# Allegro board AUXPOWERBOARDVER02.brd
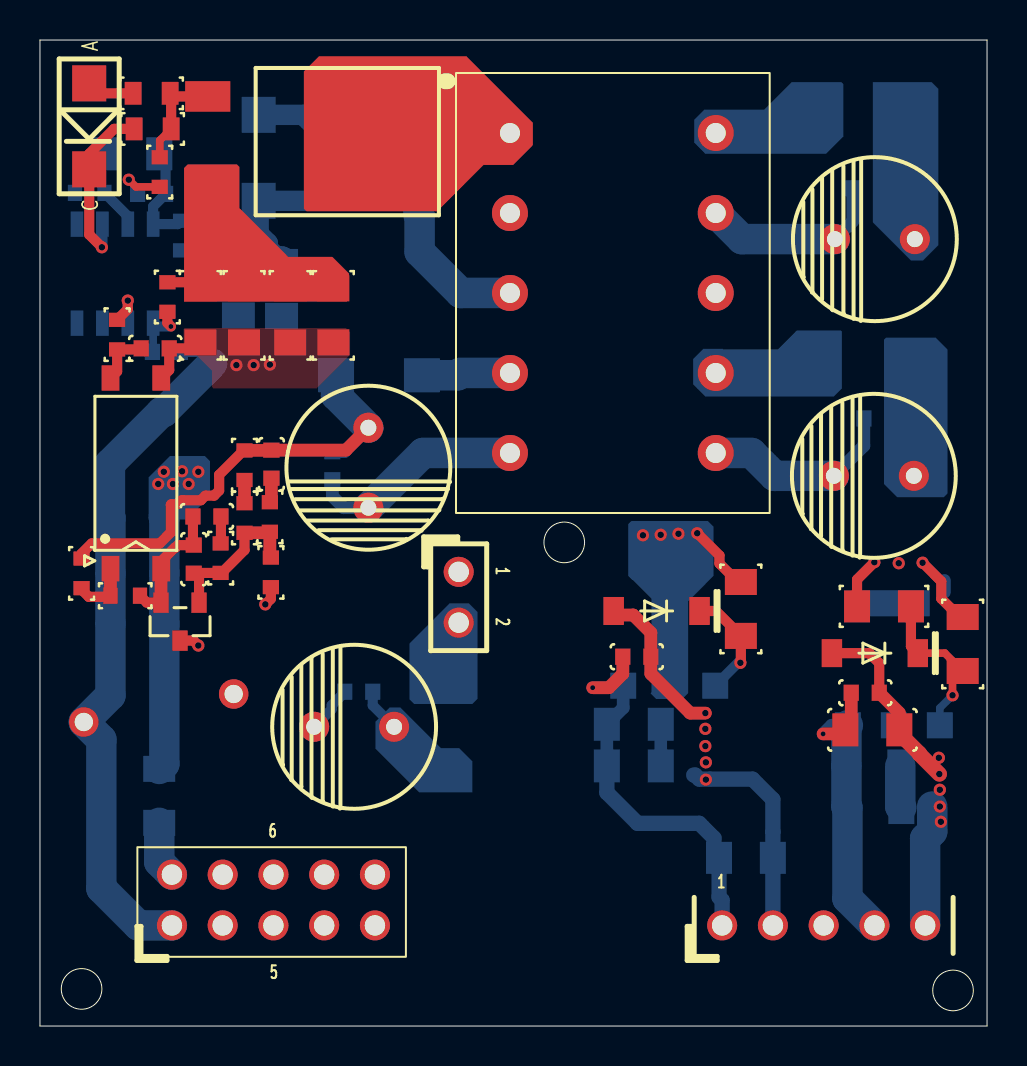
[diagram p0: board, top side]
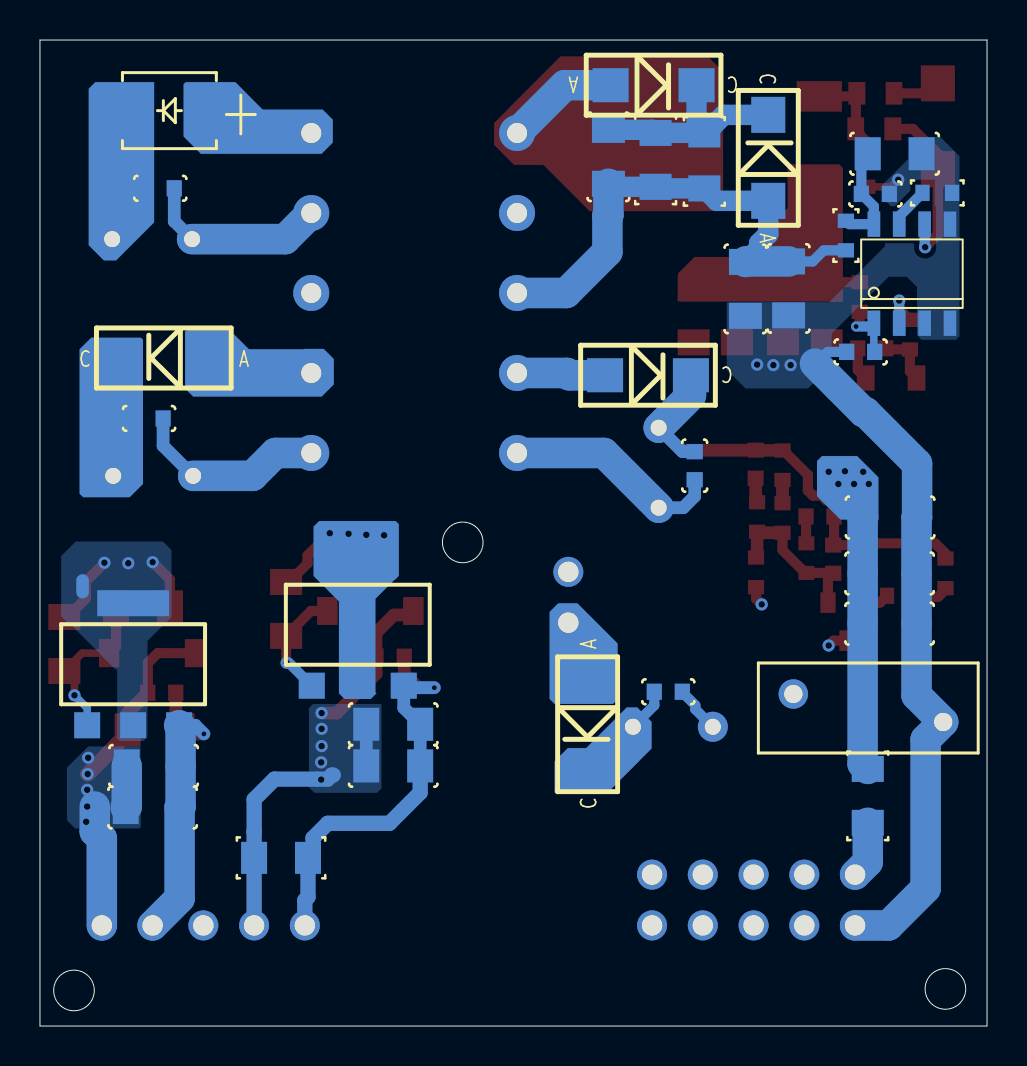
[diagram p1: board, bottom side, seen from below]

Outline 47.4 x 49.3 mm; copper layers: TOP, LAYER1, LAYER2, BOTTOM. Coordinates in mm from the lower left corner of the outline.
Outline path: circle c2.08,1.85 r1.02 ; circle c26.24,24.18 r1.02 ; circle c45.69,1.78 r1.02 ; 0,49.3 0,0 47.4,0 47.4,49.3 0,49.3

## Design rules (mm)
net group HVDC_SW: nets N16531900 N16531954
net group MVDC_SEC: nets N16668742 P_15V
net group LVDC_PRI: nets N16901051 N16901170 N16901172
net group LVDC_SEC: nets N16899196 N16899206 N16900214 N16900266
nets with their own width: min track width 0.8; nets 5V CAN_GND D_6.5V DGND N16531988 N16540909 N16669014 N16669754 N16669797 N16867048 N16899220 S_15V SGND

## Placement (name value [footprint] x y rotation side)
C22  1u  [C0603]  41.38 41.88 180 bottom
C67  1000pF  [C0603]  7.7 23.34 270 top
C95  100n  [C0603]  8.36 25.48 0 top
C111  1u  [C1206]  18.95 43.46 270 bottom
C113  220uF  [C220U25V]  16.43 27.91 90 top
C116  NC  [C0603]  11.58 28.09 270 top
C118  100p  [C0603]  6.32 33.71 0 bottom
C309  10uF  [C1206]  41.66 14.81 0 top
C310  0u1  [C0603]  41.3 16.66 0 top
C312  220uF  [C220U25V]  41.78 39.34 0 top
C313  1u  [C0603]  14.63 28.02 270 bottom
C435  10uF  [C1206]  29.72 13 0 bottom
C436  0u1  [C0603]  29.87 18.47 0 top
C438  1u  [C0603]  41.94 30.38 180 bottom
C439  220uF  [C220U25V]  41.73 27.51 0 top
C440  1u  [C0603]  15.95 16.71 180 bottom
C441  220uF  [C220U25V]  15.72 14.96 0 top
C442  10uF  [C1206]  41.71 13 0 bottom
C443  10uF  [C1206]  29.72 15.09 0 bottom
C445  10uF  [C1206]  41.76 10.92 0 bottom
C448  0.1u  [C0603]  5.59 41.61 180 bottom
C450  1n  [C0603]  5.77 33.88 0 top
C451  10uF  [C1206]  12.09 36.86 270 bottom
C452  10uF  [C1206]  4.85 25.43 180 bottom
C453  10uF  [C1206]  4.88 22.63 180 bottom
C454  10uF  [C1206]  9.93 36.88 270 bottom
C455  10uF  [C1206]  4.88 20.12 180 bottom
C456  10u  [C1206]  4.62 43.61 180 bottom
C688  220P  [Y1]  5.94 15.9 180 bottom
D25  1N4148WQ-7-F  [SMA]  16.69 47.04 0 bottom
D30  LED277_SCHOTTKY_40V_3A_SMB  [SMB]  40.92 45.77 0 bottom
D32  F6165CT-ND  [SMA]  10.95 43.41 270 bottom
D35  NC  [SMA]  2.46 44.98 90 top
D39  150V_3A  [SMA]  16.97 32.54 0 bottom
D329  LED277_SCHOTTKY_40V_3A_SMB  [SMA]  41.2 33.4 180 bottom
D330  LED277_SCHOTTKY_40V_3A_SMB  [SMA]  19.99 15.09 90 bottom
J344  CON2  [CON_2MM54_2X1]  20.95 21.44 270 top
J346  CON10A  [CON_2MM54_5X2]  9.14 6.3 0 top
J347  CON5  [CON_2MM54_5X1]  40.49 5.03 0 top
Q302  PBSS306NZ  [SOT-223]  42.73 18.09 180 bottom
Q330  PBSS306NZ  [SOT-223]  31.49 20.07 180 bottom
Q331  IPD220N06L3G  [TO252AB]  13.46 44.22 270 top
R11  1k  [R0603]  6.38 36.45 270 top
R37  100  [R0805]  5.64 44.86 0 top
R38  0.082  [R1206]  10.21 35.53 90 top
R39  0.082  [R1206]  8.03 35.53 90 top
R45  1.5k  [R0603]  4.27 21.51 180 top
R46  NC  [R0603]  11.51 25.45 90 top
R47  3.3k  [R0603]  10.24 25.4 90 top
R48  5.1K  [R0603]  11.56 22.68 90 top
R52  NC  [R0805]  5.59 46.63 0 top
R54  10k  [R0603]  5.99 42.7 90 top
R56  3k  [R0603]  9.04 23.39 90 top
R108  22k  [R0603]  10.24 28.04 90 top
R409  1k  [R1206]  35.08 20.85 270 top
R526  4.7k  [R0603]  2.08 22.63 270 top
R527  0.082  [R1206]  12.52 35.53 90 top
R528  150k  [R0603]  2.49 41.66 180 bottom
R530  1k  [R0603]  3.86 34.57 90 top
R531  0  [R1206]  5.97 11.51 90 bottom
R532  0.082  [R1206]  14.68 35.53 90 top
R535  0  [R0603]  7.06 39.52 90 bottom
R536  1k  [R1206]  46.18 19.1 270 top
R537  1k  [R1206]  42.24 20.98 0 top
R538  10k  [R1206]  14.15 43.23 90 bottom
R539  10k  [R1206]  16.59 43.31 90 bottom
R540  1k  [R1206]  35.33 8.41 0 bottom
T12  CR6600FZ1  [TPRIAUX]  23.52 28.65 0 top
U9  AZ431AN-ATRE1  [SOT23_1-32]  7.01 20.22 180 top
U11  TCLT1003  [OPTO-SOP-4L]  4.8 27.64 90 top
U22  LM3478  [SOIC8]  3.76 37.62 90 bottom
ZD300  15V  [SOD-123]  41.78 18.64 0 top
ZD326  5.6V  [SOD-123]  30.86 20.75 0 top

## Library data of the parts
C22 C67 C313 C438 C440 = LEC007_0805_50V
C95 C116 C448 C450 C456 = LEC006_0603_50V
C111 = LEC052_1206_0.033UF_630V
C113 C312 C439 C441 = LEC231_AL_470UF_25V_0: alternate symbols: (CRAD-10ODX16L-H,CRAD-10ODX16L-H-1)
C118 = LEC003_0603_16V
C309 C435 C442 C443 C445 = CAP POL
C310 C436 = CAP NP
C451-C455 = LEC034_AL_47UF_25V: alternate symbols: (CRAD-5ODX11L-H,CRAD-5ODX11L-H-1)
C688 = CAP NP: Tolerance: #TOL; User Part Number: HAMP
D25 D35 = LED005_1000V_1A_DO214AC_3
D30 D39 D329 D330 = LED277_SCHOTTKY_40V_3A_SMB_0
D32 = LED188_TVS_350V_600W_SMB_0
J344 = CON2
J346 = CON10A
J347 = CON5
Q302 Q330 = NPN BCE_1
Q331 = 2N7002/SOT_1
R11 R45-R48 R54 R56 R108 R528 R530 R535-R539 = LER001_0603_1
R37-R39 R52 R527 R531 R532 = LER003_0805_1
R409 R540 = R
R526 = LER005_1206_1
T12 = CREE-6600-FZ1_5
U9 = LEU094_ZTL431AFTA_SOT23_2
U11 = LEU169_TCLT1003_SOP-4L
U22 = 1EDI60N12AF-DS_3: Tolerance: ***; User Part Number: ***
ZD300 ZD326 = DIODE ZENER

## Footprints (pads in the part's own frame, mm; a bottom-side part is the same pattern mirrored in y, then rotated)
C220U25V
  round 1.501 hole 0.8: 1(-2,0) 2(2,0)
C0603
  rect 0.759x0.81 smd: 1(-0.701,0) 2(0.701,0)
C1206
  rect 1.3x1.651 smd: 1(-1.349,0) 2(1.349,0)
CON_2MM54_2X1
  round 1.501 hole 1.021: 1(-1.27,0) 2(1.27,0)
CON_2MM54_5X1
  round 1.501 hole 1.021: 1(-6.35,0) 2(-3.81,0) 3(-1.27,0) 4(1.27,0) 5(3.81,0)
CON_2MM54_5X2
  round 1.501 hole 1.021: 1(-2.54,-1.27) 2(-2.54,1.27) 3(0,-1.27) 4(0,1.27) 5(2.54,-1.27) 6(2.54,1.27) 7(5.08,-1.27) 8(5.08,1.27) 9(7.62,-1.27) 10(7.62,1.27)
OPTO-SOP-4L
  rect 1.27x0.889 smd: 1(-4.765,1.27) 2(-4.765,-1.27) 3(4.765,-1.27) 4(4.765,1.27)
R0603
  rect 0.711x0.81 smd: 1(-0.739,0) 2(0.739,0)
R0805
  rect 0.841x1.14 smd: 1(-0.927,0) 2(0.927,0)
R1206
  rect 1.3x1.6 smd: 1(-1.349,0) 2(1.349,0)
SMA
  rect 1.801x1.699 smd: 1(2.149,0) 2(-2.149,0)
SMB
  rect 2.291x2.54 smd: 1(-1.999,0) 2(1.999,0)
SOD-123
  rect 1.021x1.4 smd: 1(-2.149,0) 2(2.149,0)
SOIC8
  rect 1.27x0.635 smd: 1(-2.477,1.905) 2(-2.477,0.635) 3(-2.477,-0.635) 4(-2.477,-1.905) 5(2.477,-1.905) 6(2.477,-0.635) 7(2.477,0.635) 8(2.477,1.905)
SOT23_1-32
  rect 0.762x1.016 smd: 1(0,0.95) 2(0.95,-0.95) 3(-0.95,-0.95)
SOT-223
  rect 1.3x1.3 smd: 1(-2.301,-3.051) 2(0,-3.051) 3(2.301,-3.051)
  rect 3.599x1.3 smd: 4(0,3.051)
TO252AB
  rect 1.524x2.261 smd: A1(-2.261,-5.067) A2(2.261,-5.067)
  rect 6.731x6.223 smd: K(0,3.086)
TPRIAUX
  round 1.801 hole 1.001: 1(0,15.999) 2(0,11.999) 3(0,8.001) 4(0,4) 5(0,0) 6(10.3,0) 7(10.3,4) 8(10.3,8.001) 9(10.3,11.999) 10(10.3,15.999)
Y1
  round 1.473 hole 0.914: 1(-3.75,0.7) 2(3.75,-0.7)

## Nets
5V: C435.1 C436.1 C443.1 J347.1 Q330.3(E) R540.1
DGND: C440.2 C441.1(2) J344.1 J346.10
PGND_SIGNAL: C113.1(2) C313.2 C688.1 J346.5 R48.1 T12.5 U9.1(A)
SGND: C22.2 C309.2 C310.2 C312.1(2) C442.2 C445.2 J347.5 T12.9 ZD300.1(ANODE)
AUX_DC+: J346.2 R531.1
CAN_GND: C435.2 C436.2 C438.2 C439.1(2) C443.2 J347.2 R540.2 T12.6 ZD326.1(ANODE)
CS1: Q331.A2(SOURCE) R11.1 R38.2 R39.2 R527.2 R532.2
D_6.5V: C440.1 C441.2(1) D330.2(K) J346.9
ISGND: C118.2 C448.2 C450.2 C451.2 C452.2 C453.2 C454.2 C455.2 C456.2 C688.2 J346.1 R38.1 R39.1 R54.1 R527.1 R528.2 R532.1 U11.3 U22.3(FB) U22.4(AGND) U22.5(PGND)
P_15V: C113.2(1) C116.1 C313.1 D39.2(K) J346.6 R108.2 R526.1
S_15V: C309.1 C310.1 C442.1 C445.1 J347.4 Q302.3(E)
N16531834: D39.1(A) T12.4
N16531864: C111.2 C451.1 C452.1 C453.1 C454.1 C455.1 D32.1 R531.2 R535.1 R538.1 R539.1 T12.3
N16531900: C111.1 D25.2 D32.2 R538.2 R539.2
N16531954: D25.1 Q331.K(DRAIN) T12.1
N16531988: C22.1 C312.2(1) D30.2(K) Q302.2(C) Q302.4(C1) R536.1 R537.1
N16540909: Q302.1(B) R536.2 R537.2 ZD300.2(CATHODE)
N16668742: C438.1 C439.2(1) D329.2(K) Q330.2(C) Q330.4(C1) R409.1
N16669014: Q330.1(B) R409.2 ZD326.2(CATHODE)
N16669754: D329.1(A) T12.7
N16669797: D30.1(A) T12.10
N16867048: D330.1(A) J344.2
N16899196: C67.2 R46.1 R47.1 R48.2 R56.1 U9.3(REF)
N16899206: C116.2 R46.2
N16899220: R47.2 R108.1
N16900053: R45.2 R526.2 U11.1
N16900214: C67.1 C95.1 R45.1 U9.2(K) U11.2
N16900266: C95.2 R56.2
N16901051: C118.1 R11.2 U22.1(IS)
N16901170: D35.2 R37.1 U22.6(DR)
N16901172: Q331.A1(GATE) R37.2 R52.2 R54.2
N16903870: D35.1 R52.1
N16903956: R528.1 U22.7(FA/SD)
N16904160: C448.1 C456.1 R535.2 U22.8(VIN)
N16915016: R530.2 U22.2(COMP)
N16915019: C450.1 R530.1 U11.4

Pads without a net: J346 3 4 7 8; J347 3; T12 2 8

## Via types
v1: diameter 0.61, hole 0.33, TOP to BOTTOM, 33 vias
v2: diameter 0.46, hole 0.249, TOP to BOTTOM, 3 vias

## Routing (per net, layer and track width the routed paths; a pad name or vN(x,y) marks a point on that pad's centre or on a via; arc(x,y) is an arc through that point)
5V: length 20.7
  TOP w0.635: v2(27.66,16.92) 28.47,16.92 29.17,17.61 C436.1
  BOTTOM w0.635: v2(27.66,16.92) 29.09,16.92 Q330.3 29.19,15.91 C443.1 C435.1
  BOTTOM w0.762: J347.1 34.14,6.29 33.98,6.45 R540.1 33.73,8.66 33.73,9.4 32.99,10.13 29.9,10.13 28.37,11.67 C435.1
DGND: length 24.4
  LAYER1 w1.524: J344.1 16.56,22.71 13.72,19.87 C441.1 16.8,11.89 16.8,9.24 16.76,9.21 J346.10
  BOTTOM w0.508: C440.2 15.25,16.69 14.6,16.04 14.6,15.84 C441.1
PGND_SIGNAL: length 13.1
  TOP w0.508: v1(7.92,19.02) 7.68,19.27 U9.1 ; R48.1 11.56,21.36 v1(11.28,21.08)
  BOTTOM w0.635: C113.1 15.2,25.91 14.63,26.49 C313.2
  BOTTOM w1.524: T12.5 19.17,28.65 C113.1
SGND: length 57.7
  TOP w0.508: ZD300.1 41.5,18.64 42,18.15 C310.2
  TOP w0.635: C310.2 43,15.66 C309.2
  TOP w0.762: v1(45.01,12.6) 44.02,13.59 44.02,13.62 43,14.63 C309.2
  LAYER1 w1.524: 43.61,12.09 39.45,16.26 39.45,23.7 41.69,25.94 41.69,37.44 C312.1
  BOTTOM w0.635: C22.2 40.68,40.24 C312.1
  BOTTOM w1.524: C445.2 43.06,10.97 C442.2 ; 44.65,10.97 44.65,9.73 44.3,9.38 J347.5 ; T12.9 35.13,39.34 C312.1
  vias: v1(44.98,13.41) v1(45.03,11.81) v1(45.03,10.97) v1(45.09,10.21)
AUX_DC+: length 2.9
  BOTTOM w1.524: R531.1 5.97,8.2 J346.2
CAN_GND: length 48.2
  TOP w0.635: ZD326.1 28.92,20.55 29.69,20.55 30.57,19.67 C436.2 30.57,17.61 32.54,15.65 v1(33.3,15.65)
  LAYER1 w1.524: C439.1 31.78,19.55 31.78,13.44
  BOTTOM w0.635: C443.2 C435.2 31.07,12.83 ; C439.1 41.23,29.01 C438.2
  BOTTOM w0.762: J347.2 R540.2 36.68,9.72 36.68,9.72 36.68,11.33 35.66,12.34 32.99,12.34 32.79,12.55 32.72,12.55
  BOTTOM w1.524: C439.1 36.76,27.51 35.61,28.65 T12.6
  vias: v1(33.3,14.86) v1(33.3,14) v1(33.32,13.18) v1(33.32,12.32)
CS1: length 1.8
  TOP w0.508: R11.1 7.72,37.19 R39.2
D_6.5V: length 17.2
  LAYER1 w1.524: C441.2 21.13,11.56 21.13,6.27 19.89,5.03 J346.9
  BOTTOM w0.508: C441.2 16.65,16.03 C440.1
ISGND: length 39.7
  TOP w0.381: R54.1 4.8,41.96 v1(4.45,42.32)
  TOP w0.508: R39.1 7.72,33.88 C450.2 6.47,32.8 U11.3
  BOTTOM w0.508: 8.03,33.66 7.98,33.71 C118.2
  BOTTOM w1.524: J346.1 4.93,5.03 3.07,6.88 3.07,14.32 C688.2 3.53,16.53 C455.2 C453.2 3.53,25.4 C452.2 3.5,28.12 6.08,30.7 6.19,30.7 8.61,33.12
  vias: v1(9.83,33.05) v1(10.69,33.05) v1(11.51,33.07)
P_15V: length 50.3
  TOP w0.508: R108.2 10.19,28.78 8.97,27.56 8.97,26.77 8.71,26.52 8.28,26.52 8.05,26.29 7.11,26.29 7.06,26.24 7.01,26.24 6.86,26.09 6.58,26.09 6.55,26.06 6.55,24.69 5.99,24.13 2.59,24.13 2.08,23.62 R526.1
  TOP w0.635: C113.2 15.31,28.79 C116.1 11.57,28.78 R108.2
  LAYER2 w0.889: C113.2 18.72,27.63 18.72,24.43 12.03,17.74 12.03,8.88 12.04,8.86 12.04,7.92 J346.6
  BOTTOM w0.635: C313.1 15.24,28.72 C113.2
  BOTTOM w1.524: C113.2 14.82,31.53 D39.2
S_15V: length 15.2
  TOP w0.635: v2(39.19,14.6) 40.1,14.6 C309.1 40.6,15.1 C310.1
  BOTTOM w0.635: v2(39.19,14.6) 39.62,15.04 Q302.3
  BOTTOM w1.524: J347.4 40.41,6.38 C445.1 40.36,10.97 C442.1 40.36,14.96 Q302.3
N16531834: length 4.5
  BOTTOM w1.524: D39.1 20.91,32.54 21.02,32.65 T12.4
N16531864: length 58.3
  LAYER1 w1.524: T12.3 17.3,36.65 8.03,27.38 7.65,27.38
  BOTTOM w0.508: R535.1 8.17,38.78 8.72,38.23 C454.1
  BOTTOM w1.016: C111.2 18.8,41.96 R539.1 16.51,41.88 R538.1 13.53,41.26 D32.1 10.95,39.6 11.4,39.14 11.4,38.89 12.07,38.23
  BOTTOM w1.524: C452.1 6.23,25.4 C453.1 C455.1 6.23,13.11 R531.2 ; C454.1 12.07,38.23 C451.1 ; T12.3 21.06,36.65 19,38.71 19,40.52 18.95,40.57 C111.2
  vias: v1(5.92,27.1) v1(6.2,27.71) v1(6.65,27.1) v1(7.11,27.74) v1(7.44,27.1) v1(7.92,27.71)
N16531900: length 11
  BOTTOM w1.016: C111.1 16.74,44.81 R539.2 14.22,44.66 ; 14.22,44.66 R538.2 13.17,45.56 D32.2 ; 14.22,44.66 14.54,44.97 D25.2
N16531954: length 5.7
  BOTTOM w1.524: D25.1 21.13,47.04 T12.1
N16531988: length 24.9
  TOP w0.508: v1(41.76,23.19) 40.89,22.32 R537.1 ; v1(44.17,23.16) 45.11,22.23 45.11,21.37 46.03,20.45 R536.1
  LAYER1 w1.524: 45.64,22 45.64,37.48 C312.2
  BOTTOM w0.635: 45.26,22.28 45.26,21.7
  vias: v1(42.98,23.14)
N16540909: length 8.3
  TOP w0.381: v1(45.67,16.54) 45.67,17.24 R536.2 45.29,18.64 ZD300.2
  TOP w0.508: ZD300.2 43.59,18.99 R537.2
  BOTTOM w0.381: Q302.1 45.03,15.9 v1(45.67,16.54)
N16668742: length 17.2
  TOP w0.508: R409.1 34.93,22.2 34.01,23.12 34.01,23.52 v1(32.89,24.64)
  LAYER2 w1.524: C439.2 40.99,24.77 32.61,24.77 31.83,23.98
  BOTTOM w0.635: 43.3,33.4 D329.2 ; 31.72,23.34 Q330.4 31.54,23.06
  vias: v1(30.18,24.54) v1(31.06,24.56) v1(31.95,24.61)
N16669014: length 5.7
  TOP w0.508: ZD326.2 33.83,20.75 R409.2 35.08,18.19 v1(35.05,18.16)
  BOTTOM w0.508: Q330.1 34.94,18.16 v1(35.05,18.16)
N16899196: length 8.1
  TOP w0.508: U9.3 7.96,22.38 C67.2 7.71,22.65 R56.1 9.09,22.65 10.24,23.8 R47.1
  TOP w0.635: R48.2 11.51,23.47 R46.1 11.46,24.66 R47.1
N16899206: length 1.2
  TOP w0.635: C116.2 11.58,26.27 R46.2
N16899220: length 1.2
  TOP w0.635: R108.1 R47.2
N16900053: length 3
  TOP w0.508: R45.2 3.47,21.46 2.44,21.46 2.08,21.82 R526.2
  TOP w0.635: R45.2 3.53,22.87 U11.1
N16900214: length 6.7
  TOP w0.508: R45.1 5.35,21.17 U9.2 ; U11.2 6.07,23.24 6.76,23.93 6.79,23.93 6.91,24.04 C67.1 7.66,24.08 C95.1
  TOP w0.635: U9.2 6.06,22.86 U11.2
N16900266: length 1.3
  TOP w0.508: R56.2 9.06,24.15 C95.2
N16901051: length 3.2
  TOP w0.508: R11.2 6.38,35.15 v2(6.55,34.98)
  BOTTOM w0.381: 5.66,33.75 U22.1
  BOTTOM w0.508: C118.1 5.66,33.75 ; v2(6.55,34.98) 5.83,34.98 U22.1
N16901170: length 8.9
  TOP w0.508: R37.1 3.71,44.86 2.46,43.61 D35.2 2.46,39.57 v1(3.1,38.94)
  BOTTOM w0.508: U22.6 3.12,38.96 v1(3.1,38.94)
N16901172: length 5.3
  TOP w0.381: R37.2 5.99,44.28 R54.2
  TOP w0.508: 6.57,46.58 R52.2 ; 6.57,46.58 R37.2 ; 6.57,46.58 6.67,46.48 Q331.A1
N16903870: length 2.4
  TOP w0.508: R52.1 2.96,46.63 D35.1
N16903956: length 2
  BOTTOM w0.508: R528.1 4.39,40.49 U22.7
N16904160: length 5.4
  BOTTOM w0.508: C456.1 6.29,43.29 C448.1 5.66,40.98 U22.8 6.89,40.09 R535.2
N16915016: length 2.3
  TOP w0.508: v1(4.39,36.27) 4.39,35.84 R530.2
  BOTTOM w0.508: U22.2 v1(4.39,36.27)
N16915019: length 2.8
  TOP w0.508: U11.4 3.86,32.73 R530.1 5.01,33.83 C450.1

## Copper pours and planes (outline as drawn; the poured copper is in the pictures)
PGND_SIGNAL on LAYER2: 15.77,26.87 16.71,26.87 17.35,26.24 17.35,25.55 11.21,19.42 11.21,15.33 9.86,13.97 9.86,9.6 11.2,8.25 11.2,6.81 12.17,6.81 12.8,6.17 12.8,4.14 12.79,4.13 12.79,2.86 12.41,2.48 7.96,2.48 7.59,2.84 7.59,10.9 6.53,11.96 6.53,20.57 12.85,26.9 15.75,26.9
SGND on BOTTOM: 42.37,13.97 44.98,13.97 46.05,12.9 46.05,10.29 45.64,9.88 42.42,9.88 42.35,9.96
SGND on LAYER1: 42.52,14.22 46.15,14.22 46.51,13.87 46.51,9.75 46.25,9.5 42.49,9.5 42.29,9.7 42.27,9.7 42.27,13.97
CAN_GND on BOTTOM: 30.3,16.1 33.73,16.1 33.93,15.9 33.93,11.94 33.66,11.66 30.53,11.66 30.3,11.89
CAN_GND on LAYER1: 30.35,16.1 34.29,16.1 34.8,15.6 34.8,12.17 34.01,11.38 30.53,11.38 30.05,11.86 30.05,15.8
CS1 on TOP (solid shape): 9.98,42.95 9.98,40.89 12.42,38.46 14.63,38.46 15.47,37.62 15.47,36.35 15.34,36.22 7.21,36.22 7.21,42.9 7.39,43.08 9.86,43.08
D_6.5V on BOTTOM (solid shape): 20.07,13.89 20.98,13.89 21.64,13.23 21.64,11.68 18.97,11.68 16.79,13.87 16.79,15.21 17.5,15.93 18.03,15.93
ISGND on TOP: 15.52,34.7 15.52,33.55 13.84,31.88 8.69,31.88 8.61,31.95 8.61,32.77 7.85,33.53 7.21,33.53 7.19,33.55 7.19,34.85 7.24,34.9 15.32,34.9
ISGND on BOTTOM: 7.9,36.2 5.11,38.99 5.11,39.14 3.58,39.14 3.35,39.37 3.35,40.39 3.86,40.89 4.72,40.89 5.26,41.43 5.26,42.04 3.94,43.36 3.94,44.45 2.34,44.45 1.37,43.48 1.37,34.49 1.55,34.32 3.28,34.32 3.51,34.54 3.51,36.96 4.01,37.47 4.93,37.47 7.77,34.62 7.77,33.07 8.97,31.88 12.09,31.88 13.03,32.82 13.03,36.14 12.98,36.2
N16531864 on BOTTOM (solid shape): 8.51,28.24 8.51,26.49 7.34,25.32 5.44,25.32 5.44,27.43 6.5,28.5 8.25,28.5
N16531864 on LAYER1: 5.44,25.55 5.44,27.76 6.6,28.93 8.71,28.93 9.04,28.6 9.04,26.92 7.39,25.27 5.71,25.27
N16531954 on TOP (solid shape): 24.66,45.16 24.66,44.04 23.67,43.05 22.2,43.05 19.89,40.74 13.34,40.74 13.21,40.87 13.21,47.73 13.97,48.49 21.34,48.49
N16531988 on BOTTOM (solid shape): 44.96,46.86 44.96,39.04 44.2,38.28 43.59,38.28 41.68,40.18 41.68,47.19 44.63,47.19
N16531988 on BOTTOM: 46.33,20.49 45.93,20.09 45.87,20.09 43.61,17.83 43.54,17.83 43.54,14.48 43.59,14.43 43.41,14.25 42.21,14.25 42.01,14.45 42.01,19.25 40.82,20.45 40.82,23.8 41.25,24.23 45.59,24.23 46.33,23.49
N16531988 on LAYER1: 40.87,20.47 40.72,20.62 40.72,23.42 41.48,24.18 45.77,24.18 46.56,23.39 46.56,20.7 46.33,20.47
N16668742 on BOTTOM (solid shape): 45.42,33.83 45.42,26.62 45.24,26.44 42.9,26.44 42.24,27.1 42.24,34.32 42.34,34.42 44.83,34.42
N16668742 on BOTTOM (solid shape): 33.71,24.97 33.71,22.5 32.44,21.23 32.44,16.64 32.16,16.36 30.84,16.36 30.56,16.64 30.61,16.69 30.61,21.36 29.67,22.3 29.64,22.3 29.44,22.5 29.44,25.1 29.59,25.25 33.43,25.25
N16668742 on LAYER2 (solid shape): 33.71,24.94 33.71,22.5 33.5,22.3 29.64,22.3 29.46,22.48 29.46,25.1 29.64,25.27 33.38,25.27
N16669754 on BOTTOM (solid shape): 40.13,34.72 40.13,31.88 39.73,31.47 33.3,31.47 32.69,32.08 32.69,33.35 33.2,33.86 34.16,33.86 34.19,33.83 36.93,33.83 37.87,34.77 40.08,34.77
N16669797 on BOTTOM (solid shape): 40.21,47.09 40.21,44.48 39.34,43.61 33.3,43.61 32.74,44.17 32.74,45.31 33.25,45.82 36.25,45.82 37.62,47.19 40.11,47.19
N16867048 on BOTTOM (solid shape): 21.89,20.7 21.89,16.36 21.64,16.1 18.72,16.1 18.49,16.33 18.49,19.13 20.5,21.13 21.46,21.13

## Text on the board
BOTTOM: ARTWORK BOTTOM
Board Geometry/Soldermask Bottom: SOLDERMASK BOTTOM
Package Geometry/Pastemask Bottom: PASTEMASK BOTTOM
Ref Des/Silkscreen Bottom: SILKSCREEN BOTTOM
TOP: ARTWORK TOP
Board Geometry/Soldermask Top: SOLDERMASK TOP
Package Geometry/Pastemask Top: PASTEMASK TOP
Ref Des/Silkscreen Top: SILKSCREEN TOP
LAYER1: ARTWORK LAYER02
LAYER2: ARTWORK LAYER03
DIMENSION: FAB DRAWING
DEVICE_TYPE_BOTTOM: PRIMARY SIDE
TOLERANCE_BOTTOM: SECONDARY SIDE
User.11: FIGURE | SIZE | 9.800000000000001 | 13.0 | 31.5 | 36.0 | 39.4 | 40.2 | DRILL CHART: TOP to BOTTOM | ALL UNITS ARE IN MILS | TOLERANCE | +0.0/-0.0 | +3.1/-3.1 | PLATED | QTY | 3 | 33 | 8 | 2 | 10 | 17
